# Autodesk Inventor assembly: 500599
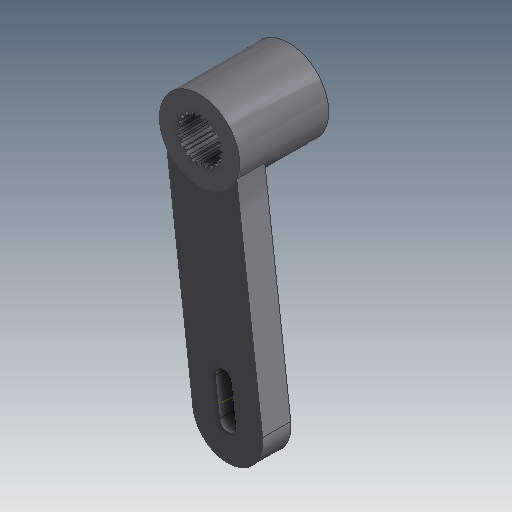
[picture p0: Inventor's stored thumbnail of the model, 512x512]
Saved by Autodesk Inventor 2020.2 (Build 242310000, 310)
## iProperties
Created: 2000-02
Part Number: 500599
Document SubType Name: Assembly
Designer: sspink
Mass: 2098.81 g
Surface Area: 520.87 cm^2
Volume: 268.063 cm^3
Density: 7.82954 g/cm^3
Control State: 0
Checked Out: False
Master: False
Shininess: 0.0
Length Units: 11272
Angle Units: 11279
Time Units: 11290
Mass Units: 11286
Length Display Precision: 3
Angle Display Precision: 2
Compacted: True
Dimensions: 8,7x2,5x3 in
Mass: 4,627 lb
Density: 0.0
Volumn: 0.0
Area: 0.0
PropertySet Name: Model Information
Author: sspink
Revision Number: -
Title: 500599
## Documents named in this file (4)
- D:\07 - DEMODATEN\OTX 2019 - Dataset - UPDATE - Dez2019\Designs\07-Packing machine\500599.iam
- D:\07 - DEMODATEN\OTX 2019 - Dataset - UPDATE - Dez2019\Designs\07-Packing machine\Parts\ADSK-011560.ipt
- D:\07 - DEMODATEN\OTX 2019 - Dataset - UPDATE - Dez2019\Designs\07-Packing machine\Parts\ADSK-011559.ipt
- D:\07 - DEMODATEN\OTX 2019 - Dataset - UPDATE - Dez2019\Content Center Files\de-DE\ISO 4026\ISO 4026 - M10 x 12 - ISO.ipt
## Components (4 placed, 3 different names)
1. ADSK-011559:1 — Fluchtend:2, Mate:1, Winkel:1, Passend:2, Tangential:1, Passend:3, Tangential:2
2. ADSK-011560:1 — Fluchtend:2, Mate:1, Winkel:1
3. ISO 4026 M10 x 12:1 — Passend:2, Tangential:1
4. ISO 4026 M10 x 12:2 — Passend:3, Tangential:2
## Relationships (7: Mate 3, Tangent 2, Flush 1, Angle 1)
- Fluchtend:2 [Flush]: ADSK-011559:1 ↔ ADSK-011560:1
- Mate:1: ADSK-011559:1 ↔ ADSK-011560:1
- Winkel:1 [Angle]: ADSK-011559:1 ↔ ADSK-011560:1
- Passend:2 [Mate]: ADSK-011559:1 ↔ ISO 4026 M10 x 12:1
- Tangential:1: ADSK-011559:1 ↔ ISO 4026 M10 x 12:1
- Passend:3 [Mate]: ADSK-011559:1 ↔ ISO 4026 M10 x 12:2
- Tangential:2: ADSK-011559:1 ↔ ISO 4026 M10 x 12:2
